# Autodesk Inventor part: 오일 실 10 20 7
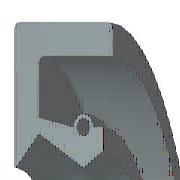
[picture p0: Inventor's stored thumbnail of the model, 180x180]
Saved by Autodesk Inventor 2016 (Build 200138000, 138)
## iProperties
IsCustomPart: 1
Created: 2012-02
Part Number: 오일 실 10 20 7
Material: 고무
Description: 오일-실
Document SubType Name: Modeling
Standard: KS B 2804
Designer: mduedu
Standards Organization: KS
Language: ko-KR
Size Designation: D - 10 20 7
Categories: <MemberInstance><Categories><Category DisplayName="샤프트 부품" InternalName="7f7aeb1f-a693-4053-b835-cee3144e0d98" Mnemonic="SHFT"><Category DisplayName="실링" Intern
Density: 0.93 g/cm^3
Appearance: 고무 - 검은색 - 버전 1.1
Author: mduedu
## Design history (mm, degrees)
revolve "본체" stored, may be unused: angle "d17" = 90 deg
revolve "스프링1" stored, may be unused: angle "d18" = 90 deg
body "Solid1"
sketch "스케치1"
  geometry: L1 (0, 10)-(7, 10); L2 (7, 8.25)-(1.75, 8.25); L3 (1.75, 6.75)-(4.9, 5); L4 (4.9, 5)-(0, 5); L5 (0, 0)-(9.586, 0) reference; L6 (4.9, 5)-(6.3, 5.875); L7 (0, 18)-(0, -3) reference; L8 (-1.941, 0)-(11.507, 0) reference; L9 (4.2, 7.1)-(1.75, 7.59); L10 (1.75, 7.59)-(1.75, 8.25); L11 (0, 10)-(0, 5.088); L12 (4.9, 5)-(0, 5); L13 (1.75, 6.75)-(0.152, 5.028); L14 (7, 10)-(7, 8.25); L15 (5.6, 7.1)-(6.3, 7.1); L16 (6.3, 7.1)-(6.3, 5.875); C1 r 0.455 at (4.9, 7.1); A1 r 0.7 centre (4.9, 7.1) between (5.6, 7.1) and (4.2, 7.1); A2 r 0.088 centre (0.088, 5.088) between (0, 5.088) and (0.152, 5.028); 1 further point
  constraints: 28 end point, 5 horizontal alignment, 5 point on line, 4 point on circle, 4 vertical alignment, 3 centre point, 3 tangent, 2 collinear, 2 horizontal, 2 perpendicular, 1 coincident, 1 parallel
  dimensions: "d0" = 20 diameter of L1 L5 (= SD2); "d1" = 1.75 distance of L1.end L2.start (= SD); "d2" = 0.91 diameter of C1 (= SPDI); "d3" = 1.4 diameter of A1 (= SPDA); "d4" = 10 diameter of L3.end L5 (= NND); "d5" = 13.5 diameter of L3.start L5 (= TKDM); "d7" = 15.18 diameter of L9.end L5 (= TKDM + 0.24 x SWDT); "d8" = 1.75 distance between parallel lines of L11 L10 (= SD); "d9" = 4.9 distance from line of L11 C1.centre (= SPDST); "d10" = 14.2 diameter of C1.centre L5 (= HLDM); "d11" = 0.0875 radius of A2 (= 0.25 x LAB); "d12" = 6.3 distance between parallel lines of L11 L16 (= SDI); "d13" = 11.75 diameter of L6.end L5 (= ABDM); "d14" = 7 distance from line of L11 L1.end (= SWDT)
fillet "모깎기1" dims "d6" = 0.3 (= RR)
other parameters: "SD2" = 20 [user parameter; used in 1 equation term], "SWDT" = 7 [user parameter; used in 2 equation terms], "RR" = 0.3 [user parameter; used in 1 equation term], "SD" = 1.75 [user parameter; used in 2 equation terms], "NND" = 10 [user parameter; used in 1 equation term], "SPDA" = 1.4 [user parameter; used in 1 equation term], "SPDI" = 0.91 [user parameter; used in 1 equation term], "TKDM" = 13.5 [user parameter; used in 2 equation terms], "HLDM" = 14.2 [user parameter; used in 1 equation term], "ABDM" = 11.75 [user parameter; used in 1 equation term], "SDI" = 6.3 [user parameter; used in 1 equation term], "SPDST" = 4.9 [user parameter; used in 1 equation term], "LAB" = 0.35 [user parameter; used in 1 equation term], "d15" = 0, "d16" = 0, "d19" = 0
